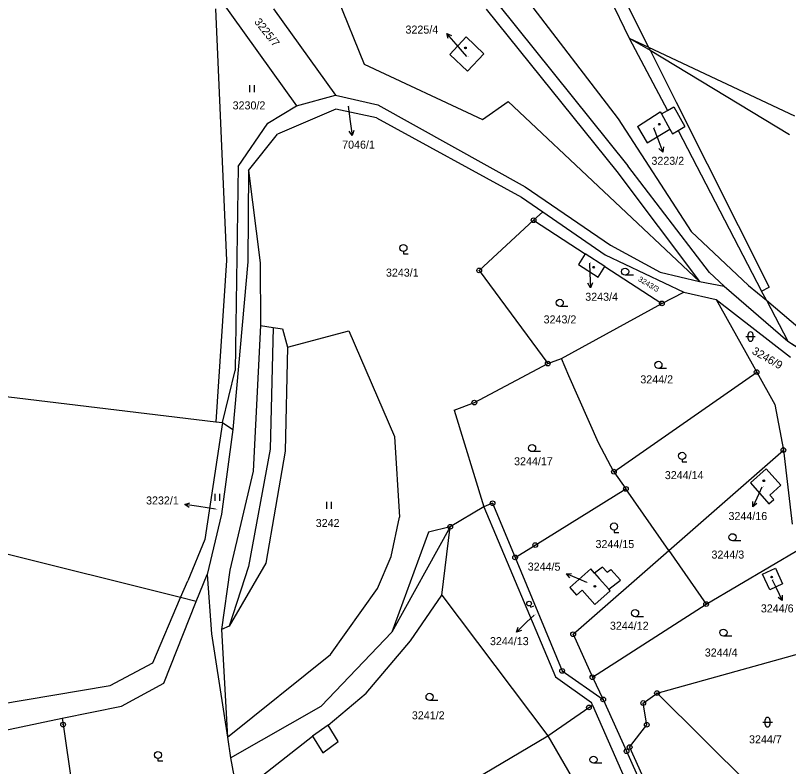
# Model space of a CAD drawing. Extents: x -593183 to -588034, y -1130415 to -1124994.
# Drawn here: x -592665.8 to -592501.6, y -1127991.1 to -1127831.6 of the extents above; entities that cross this region are included whole.
import ezdxf

# ---------------------------------------------------------------- set-up
doc = ezdxf.new("R2010")
doc.units = 0
for name, color, linetype in [('Vrstva 1', 7, 'Continuous'), ('Vrstva 16', 7, 'Continuous'), ('Vrstva 18', 7, 'Continuous'), ('Vrstva 19', 7, 'Continuous'), ('Vrstva 24', 7, 'Continuous'), ('Vrstva 25', 7, 'Continuous'), ('Vrstva 4', 7, 'Continuous')]:
    doc.layers.add(name, color=color, linetype=linetype)

msp = doc.modelspace()

# ---------------------------------------------------------------- linework, layer by layer
at = {"layer": 'Vrstva 1'}
for p, q in [((-592586.82, -1127789.77), (-592537.75, -1127853.56)), ((-592546.51, -1127808.32), (-592531.34, -1127838.36)), ((-592604.42, -1127810.45), (-592591.77, -1127841.97)), ((-592548.28, -1127810.16), (-592535.41, -1127836.44)), ((-592623.45, -1127826.59), (-592606.13, -1127850.85)), ((-592563.39, -1127829.08), (-592535.76, -1127863.57)), ((-592623.29, -1127830.23), (-592621.01, -1127883.66)), ((-592611, -1127830.22), (-592597.81, -1127848.59)), ((-592565.79, -1127830.28), (-592538.07, -1127864.74)), ((-592573.57, -1127839.96), (-592570.08, -1127836.18)), ((-592570.08, -1127836.18), (-592566.29, -1127839.82)), ((-592535.41, -1127836.44), (-592527.31, -1127851.81)), ((-592531.34, -1127838.36), (-592531.01, -1127839.01)), ((-592531.01, -1127839.01), (-592501.41, -1127856.93)), ((-592531.01, -1127839.01), (-592525.43, -1127850.05)), ((-592569.8, -1127843.47), (-592573.57, -1127839.96)), ((-592566.29, -1127839.82), (-592569.8, -1127843.47)), ((-592591.77, -1127841.97), (-592566.57, -1127853.74)), ((-592606.13, -1127850.85), (-592597.81, -1127848.59)), ((-592597.81, -1127848.59), (-592588.81, -1127850.6)), ((-592612.19, -1127854.48), (-592606.13, -1127850.85)), ((-592588.81, -1127850.6), (-592557.52, -1127868.04)), ((-592566.57, -1127853.74), (-592561.15, -1127849.89)), ((-592561.15, -1127849.89), (-592520.53, -1127888.15)), ((-592525.43, -1127850.05), (-592505.68, -1127889.36)), ((-592597.77, -1127851.54), (-592610.15, -1127856.84)), ((-592589.1, -1127853.39), (-592597.77, -1127851.54)), ((-592533.7, -1127855.19), (-592528.84, -1127852.1)), ((-592528.84, -1127852.1), (-592528.59, -1127852.54)), ((-592528.59, -1127852.54), (-592527.31, -1127851.81)), ((-592527.31, -1127851.81), (-592525.96, -1127851.05)), ((-592525.96, -1127851.05), (-592523.6, -1127855.21)), ((-592589.1, -1127853.39), (-592558.33, -1127870.19)), ((-592537.75, -1127853.56), (-592522.28, -1127877.52)), ((-592618.53, -1127863.68), (-592612.19, -1127854.48)), ((-592533.7, -1127855.19), (-592531.62, -1127858.66)), ((-592531.62, -1127858.66), (-592526.84, -1127855.8)), ((-592526.84, -1127855.8), (-592526.24, -1127856.8)), ((-592525.07, -1127856.1), (-592523.6, -1127855.21)), ((-592616.31, -1127864.53), (-592610.15, -1127856.84)), ((-592526.24, -1127856.8), (-592525.07, -1127856.1)), ((-592525.07, -1127856.1), (-592507.3, -1127890.18)), ((-592618.53, -1127863.68), (-592619.13, -1127907.06)), ((-592518.4, -1127886.2), (-592535.76, -1127863.57)), ((-592616.31, -1127864.53), (-592616.45, -1127883.98)), ((-592538.07, -1127864.74), (-592520.53, -1127888.15)), ((-592557.52, -1127868.04), (-592539.42, -1127880.42)), ((-592558.33, -1127870.19), (-592553.81, -1127873.31)), ((-592553.81, -1127873.31), (-592555.75, -1127875.11)), ((-592553.81, -1127873.31), (-592540.55, -1127882.46)), ((-592555.75, -1127875.11), (-592567.29, -1127885.78)), ((-592555.75, -1127875.11), (-592544.77, -1127882.24)), ((-592522.28, -1127877.52), (-592510.12, -1127889)), ((-592539.42, -1127880.42), (-592528.88, -1127886.14)), ((-592621.01, -1127883.66), (-592623.23, -1127917.93)), ((-592544.77, -1127882.24), (-592546.24, -1127884.5)), ((-592540.58, -1127884.96), (-592544.77, -1127882.24)), ((-592540.55, -1127882.46), (-592523.86, -1127890.37)), ((-592616.45, -1127883.98), (-592619.66, -1127919.53)), ((-592546.24, -1127884.5), (-592542.05, -1127887.22)), ((-592542.05, -1127887.22), (-592540.58, -1127884.96)), ((-592540.58, -1127884.96), (-592528.5, -1127892.8)), ((-592567.29, -1127885.78), (-592552.73, -1127905.56)), ((-592528.88, -1127886.14), (-592520.53, -1127888.15)), ((-592515.29, -1127889.1), (-592518.4, -1127886.2)), ((-592520.53, -1127888.15), (-592515.29, -1127889.1)), ((-592515.29, -1127889.1), (-592501.77, -1127900.77)), ((-592510.12, -1127889), (-592506.29, -1127892.12)), ((-592507.3, -1127890.18), (-592505.68, -1127889.36)), ((-592506.29, -1127892.12), (-592507.3, -1127890.18)), ((-592528.5, -1127892.8), (-592523.86, -1127890.37)), ((-592523.86, -1127890.37), (-592516.97, -1127891.93)), ((-592516.97, -1127891.93), (-592501.14, -1127904.21)), ((-592516.97, -1127891.93), (-592508.36, -1127907.36)), ((-592549.85, -1127904.45), (-592528.5, -1127892.8)), ((-592506.29, -1127892.12), (-592501.77, -1127900.77)), ((-592608.05, -1127902.07), (-592595, -1127898.63)), ((-592595, -1127898.63), (-592585.32, -1127921.02)), ((-592501.77, -1127900.77), (-592465.93, -1127923.67)), ((-592608.05, -1127902.07), (-592608.55, -1127924.16)), ((-592552.73, -1127905.56), (-592549.85, -1127904.45)), ((-592548.23, -1127908.14), (-592549.85, -1127904.45)), ((-592568.33, -1127913.85), (-592552.73, -1127905.56)), ((-592621.84, -1127918.1), (-592619.13, -1127907.06)), ((-592541.95, -1127922.42), (-592548.23, -1127908.14)), ((-592538.7, -1127928.51), (-592508.36, -1127907.36)), ((-592508.36, -1127907.36), (-592504.47, -1127914.27)), ((-592678.52, -1127911.3), (-592623.23, -1127917.93)), ((-592572.59, -1127915.48), (-592568.33, -1127913.85)), ((-592504.47, -1127914.27), (-592502.69, -1127923.91)), ((-592572.59, -1127915.48), (-592566.29, -1127935.99)), ((-592621.84, -1127918.1), (-592625.55, -1127942.92)), ((-592623.23, -1127917.93), (-592621.84, -1127918.1)), ((-592621.84, -1127918.1), (-592619.66, -1127919.53)), ((-592619.66, -1127919.53), (-592622.01, -1127937.52)), ((-592585.32, -1127921.02), (-592584.22, -1127938.14)), ((-592538.7, -1127928.51), (-592541.95, -1127922.42)), ((-592608.55, -1127924.16), (-592612.61, -1127947.94)), ((-592527.04, -1127945.25), (-592502.69, -1127923.91)), ((-592502.69, -1127923.91), (-592500.79, -1127939.63)), ((-592509.69, -1127930.86), (-592506.32, -1127927.88)), ((-592506.32, -1127927.88), (-592503.21, -1127931.4)), ((-592538.7, -1127928.51), (-592536.15, -1127932.18)), ((-592509.69, -1127930.86), (-592505.76, -1127935.32)), ((-592555.41, -1127944.09), (-592536.15, -1127932.18)), ((-592527.04, -1127945.25), (-592536.15, -1127932.18)), ((-592503.21, -1127931.4), (-592505.57, -1127933.49)), ((-592505.76, -1127935.32), (-592504.73, -1127934.41)), ((-592504.73, -1127934.41), (-592505.57, -1127933.49)), ((-592566.29, -1127935.99), (-592573.44, -1127940.22)), ((-592564.45, -1127935.22), (-592566.29, -1127935.99)), ((-592566.29, -1127935.99), (-592551.12, -1127972.04)), ((-592564.45, -1127935.22), (-592559.67, -1127946.73)), ((-592622.01, -1127937.52), (-592625.1, -1127950.32)), ((-592586.01, -1127946.54), (-592584.22, -1127938.14)), ((-592630.74, -1127955.24), (-592690.67, -1127940.34)), ((-592573.44, -1127940.22), (-592585.85, -1127962.59)), ((-592625.55, -1127942.92), (-592629.22, -1127951.69)), ((-592559.67, -1127946.73), (-592555.41, -1127944.09)), ((-592547.34, -1127963.04), (-592527.04, -1127945.25)), ((-592527.04, -1127945.25), (-592519.1, -1127956.63)), ((-592519.1, -1127956.63), (-592498.92, -1127944.73)), ((-592588.9, -1127953.28), (-592586.01, -1127946.54)), ((-592559.67, -1127946.73), (-592549.69, -1127970.8)), ((-592612.61, -1127947.94), (-592620.38, -1127961.3)), ((-592548.07, -1127953.1), (-592543.62, -1127949.14)), ((-592542.82, -1127950.04), (-592543.62, -1127949.14)), ((-592541.14, -1127948.79), (-592542.82, -1127950.04)), ((-592541.14, -1127948.79), (-592540.13, -1127949.88)), ((-592540.13, -1127949.88), (-592539.36, -1127949.26)), ((-592539.36, -1127949.26), (-592537.28, -1127951.53)), ((-592507.13, -1127950.28), (-592504.39, -1127949)), ((-592504.39, -1127949), (-592502.84, -1127952.31)), ((-592627.4, -1127956.08), (-592625.1, -1127950.32)), ((-592625.1, -1127950.32), (-592624.17, -1127962.93)), ((-592505.59, -1127953.58), (-592507.13, -1127950.28)), ((-592630.74, -1127955.24), (-592629.22, -1127951.69)), ((-592539.77, -1127953.49), (-592537.28, -1127951.53)), ((-592502.84, -1127952.31), (-592505.59, -1127953.58)), ((-592598.87, -1127967.31), (-592588.9, -1127953.28)), ((-592548.07, -1127953.1), (-592546.62, -1127954.73)), ((-592546.62, -1127954.73), (-592545.42, -1127953.66)), ((-592545.42, -1127953.66), (-592542.71, -1127956.7)), ((-592542.71, -1127956.7), (-592539.48, -1127953.82)), ((-592539.48, -1127953.82), (-592539.77, -1127953.49)), ((-592636.65, -1127969.08), (-592630.74, -1127955.24)), ((-592627.4, -1127956.08), (-592630.74, -1127955.24)), ((-592634.31, -1127973.38), (-592627.4, -1127956.08)), ((-592543.24, -1127972.16), (-592519.1, -1127956.63)), ((-592620.38, -1127961.3), (-592622.03, -1127962.01)), ((-592622.03, -1127962.01), (-592620.78, -1127984.86)), ((-592624.17, -1127962.93), (-592620.78, -1127984.86)), ((-592600.9, -1127978.32), (-592585.85, -1127962.59)), ((-592547.34, -1127963.04), (-592543.24, -1127972.16)), ((-592529.53, -1127975.52), (-592491.96, -1127965.07)), ((-592620.78, -1127984.86), (-592598.87, -1127967.31)), ((-592645.69, -1127973.89), (-592636.65, -1127969.08)), ((-592551.12, -1127972.04), (-592543.48, -1127977.55)), ((-592549.69, -1127970.8), (-592540.94, -1127976.88)), ((-592543.24, -1127972.16), (-592540.94, -1127976.88)), ((-592687.87, -1127981.06), (-592645.69, -1127973.89)), ((-592643.3, -1127978.28), (-592634.31, -1127973.38)), ((-592532.46, -1127977.63), (-592529.53, -1127975.52)), ((-592529.53, -1127975.52), (-592504.02, -1128000.74)), ((-592540.94, -1127976.88), (-592536.01, -1127987.86)), ((-592655.88, -1127980.87), (-592643.3, -1127978.28)), ((-592620.1, -1127989.27), (-592600.9, -1127978.32)), ((-592552.74, -1127984.59), (-592543.99, -1127978.58)), ((-592543.99, -1127978.58), (-592543.23, -1127978.11)), ((-592543.23, -1127978.11), (-592543.48, -1127977.55)), ((-592543.23, -1127978.11), (-592528.89, -1128010.56)), ((-592531.72, -1127982.26), (-592532.46, -1127977.63)), ((-592691.22, -1127988.24), (-592655.88, -1127980.87)), ((-592655.88, -1127980.87), (-592655.69, -1127982.21)), ((-592655.69, -1127982.21), (-592648.04, -1128035.39)), ((-592535.34, -1127986.99), (-592531.72, -1127982.26)), ((-592620.78, -1127984.86), (-592620.1, -1127989.27)), ((-592572.2, -1127996.11), (-592552.74, -1127984.59)), ((-592535.34, -1127986.99), (-592527.42, -1128004.73)), ((-592536.01, -1127987.86), (-592506.75, -1128053.34)), ((-592620.1, -1127989.27), (-592618.71, -1127997.15))]:
    msp.add_line(p, q, dxfattribs=at)
at = {"layer": 'Vrstva 16'}
for p, q in [((-592569.9, -1127840.37), (-592572.21, -1127837.74)), ((-592595.15, -1127850.92), (-592594.68, -1127854.17)), ((-592530.27, -1127855.51), (-592529.36, -1127857.86)), ((-592543.86, -1127884.22), (-592543.78, -1127886.44)), ((-592507.23, -1127931.77), (-592507.91, -1127933.24)), ((-592623.3, -1127936.47), (-592626.87, -1127935.92)), ((-592544.43, -1127952.04), (-592546.03, -1127951.36)), ((-592505.1, -1127951.48), (-592504.25, -1127953.19)), ((-592555.62, -1127958.96), (-592557.23, -1127960.49))]:
    msp.add_line(p, q, dxfattribs=at)
at = {"layer": 'Vrstva 24'}
for centre, radius in [((-592555.75, -1127875.11), 0.5), ((-592555.75, -1127875.11), 0.0327), ((-592567.29, -1127885.78), 0.5), ((-592567.29, -1127885.78), 0.0327), ((-592528.5, -1127892.8), 0.5), ((-592528.5, -1127892.8), 0.0327), ((-592552.73, -1127905.56), 0.5), ((-592552.73, -1127905.56), 0.0327), ((-592508.36, -1127907.36), 0.5), ((-592508.36, -1127907.36), 0.0327), ((-592568.33, -1127913.85), 0.5), ((-592568.33, -1127913.85), 0.0327), ((-592502.69, -1127923.91), 0.5), ((-592502.69, -1127923.91), 0.0327), ((-592538.7, -1127928.51), 0.5), ((-592538.7, -1127928.51), 0.0327), ((-592536.15, -1127932.18), 0.5), ((-592536.15, -1127932.18), 0.0327), ((-592564.45, -1127935.22), 0.5), ((-592564.45, -1127935.22), 0.0327), ((-592573.44, -1127940.22), 0.5), ((-592573.44, -1127940.22), 0.0327), ((-592555.41, -1127944.09), 0.5), ((-592555.41, -1127944.09), 0.0327), ((-592559.67, -1127946.73), 0.5), ((-592559.67, -1127946.73), 0.0327), ((-592519.1, -1127956.63), 0.5), ((-592519.1, -1127956.63), 0.0327), ((-592547.34, -1127963.04), 0.5), ((-592547.34, -1127963.04), 0.0327), ((-592549.69, -1127970.8), 0.5), ((-592549.69, -1127970.8), 0.0327), ((-592543.24, -1127972.16), 0.5), ((-592543.24, -1127972.16), 0.0327), ((-592529.53, -1127975.52), 0.5), ((-592529.53, -1127975.52), 0.0327), ((-592540.94, -1127976.88), 0.5), ((-592540.94, -1127976.88), 0.0327), ((-592532.46, -1127977.63), 0.5), ((-592543.99, -1127978.58), 0.5), ((-592543.99, -1127978.58), 0.0327), ((-592532.46, -1127977.63), 0.0327), ((-592655.69, -1127982.21), 0.5), ((-592655.69, -1127982.21), 0.0327), ((-592531.72, -1127982.26), 0.5), ((-592531.72, -1127982.26), 0.0327), ((-592535.34, -1127986.99), 0.5), ((-592535.34, -1127986.99), 0.0327), ((-592536.01, -1127987.86), 0.5), ((-592536.01, -1127987.86), 0.0327)]:
    msp.add_circle(centre, radius, dxfattribs=at)
at = {"layer": 'Vrstva 25'}
for p, q in [((-592572.21, -1127837.74), (-592574.19, -1127835.49)), ((-592616.06, -1127846.44), (-592616.06, -1127847.94)), ((-592615.04, -1127847.94), (-592615.04, -1127846.44)), ((-592594.68, -1127854.17), (-592594.25, -1127857.14)), ((-592529.36, -1127857.86), (-592528.28, -1127860.66)), ((-592583.39, -1127881.76), (-592583.39, -1127882.26)), ((-592583.39, -1127882.26), (-592582.37, -1127882.26)), ((-592543.78, -1127886.44), (-592543.68, -1127889.44)), ((-592534.55, -1127886.79), (-592536.3, -1127886.79)), ((-592548.44, -1127893.41), (-592550.19, -1127893.41)), ((-592510.66, -1127899.82), (-592508.66, -1127899.82)), ((-592510.16, -1127900.32), (-592510.16, -1127899.32)), ((-592509.16, -1127899.32), (-592509.16, -1127900.32)), ((-592527.48, -1127906.58), (-592529.23, -1127906.58)), ((-592554.31, -1127924.25), (-592556.06, -1127924.25)), ((-592524.19, -1127925.9), (-592524.19, -1127926.4)), ((-592524.19, -1127926.4), (-592523.17, -1127926.4)), ((-592623.45, -1127933.18), (-592623.45, -1127934.68)), ((-592622.43, -1127934.68), (-592622.43, -1127933.18)), ((-592507.91, -1127933.24), (-592509.17, -1127935.96)), ((-592626.87, -1127935.92), (-592629.84, -1127935.47)), ((-592599.72, -1127934.88), (-592599.72, -1127936.38)), ((-592598.7, -1127936.38), (-592598.7, -1127934.88)), ((-592538.66, -1127940.9), (-592538.66, -1127941.4)), ((-592538.66, -1127941.4), (-592537.64, -1127941.4)), ((-592511.74, -1127943.18), (-592513.49, -1127943.18)), ((-592546.03, -1127951.36), (-592548.79, -1127950.18)), ((-592504.25, -1127953.19), (-592502.91, -1127955.88)), ((-592556.49, -1127956.97), (-592556.35, -1127957.28)), ((-592556.35, -1127957.28), (-592555.72, -1127957)), ((-592557.23, -1127960.49), (-592559.4, -1127962.56)), ((-592532.43, -1127959.3), (-592534.18, -1127959.3)), ((-592513.66, -1127963.43), (-592515.41, -1127963.43)), ((-592576.1, -1127977.07), (-592577.85, -1127977.07)), ((-592507.03, -1127981.7), (-592505.03, -1127981.7)), ((-592506.53, -1127982.2), (-592506.53, -1127981.2)), ((-592505.53, -1127981.2), (-592505.53, -1127982.2)), ((-592635.54, -1127989.41), (-592635.54, -1127989.91)), ((-592635.54, -1127989.91), (-592634.52, -1127989.91)), ((-592541.27, -1127990.41), (-592543.02, -1127990.41))]:
    msp.add_line(p, q, dxfattribs=at)
for points in [[(-592573.91, -1127836.57), (-592574.19, -1127835.49), (-592573.15, -1127835.91)], [(-592593.9, -1127856.08), (-592594.25, -1127857.14), (-592594.89, -1127856.22)], [(-592528.17, -1127859.55), (-592528.28, -1127860.66), (-592529.11, -1127859.91)], [(-592543.21, -1127888.42), (-592543.68, -1127889.44), (-592544.21, -1127888.46)], [(-592628.92, -1127936.11), (-592629.84, -1127935.47), (-592628.77, -1127935.12)], [(-592508.3, -1127935.26), (-592509.17, -1127935.96), (-592509.2, -1127934.84)], [(-592548.07, -1127951.04), (-592548.79, -1127950.18), (-592547.67, -1127950.12)], [(-592502.91, -1127954.76), (-592502.91, -1127955.88), (-592503.81, -1127955.2)], [(-592558.33, -1127962.23), (-592559.4, -1127962.56), (-592559.02, -1127961.51)]]:
    msp.add_lwpolyline(points, dxfattribs=at)
for centre, radius in [((-592570.22, -1127838.53), 0.175), ((-592570.22, -1127838.53), 0.15), ((-592529.05, -1127854.74), 0.175), ((-592529.05, -1127854.74), 0.15), ((-592583.39, -1127881.01), 0.75), ((-592542.98, -1127885.1), 0.175), ((-592542.98, -1127885.1), 0.15), ((-592536.3, -1127886.04), 0.75), ((-592550.19, -1127892.66), 0.75), ((-592529.23, -1127905.83), 0.75), ((-592556.06, -1127923.5), 0.75), ((-592524.19, -1127925.15), 0.75), ((-592506.84, -1127930.44), 0.175), ((-592506.84, -1127930.44), 0.15), ((-592538.66, -1127940.15), 0.75), ((-592513.49, -1127942.43), 0.75), ((-592505.19, -1127950.88), 0.175), ((-592505.19, -1127950.88), 0.15), ((-592542.73, -1127952.86), 0.175), ((-592542.73, -1127952.86), 0.15), ((-592556.69, -1127956.52), 0.502), ((-592534.18, -1127958.55), 0.75), ((-592515.41, -1127962.68), 0.75), ((-592577.85, -1127976.32), 0.75), ((-592635.54, -1127988.66), 0.75), ((-592543.02, -1127989.66), 0.75)]:
    msp.add_circle(centre, radius, dxfattribs=at)
for centre, start, end in [((-592509.66, -1127899.32), 90, 180), ((-592509.66, -1127899.32), 0, 90), ((-592509.66, -1127900.32), 180, 270), ((-592509.66, -1127900.32), 270, 0), ((-592506.03, -1127981.2), 90, 180), ((-592506.03, -1127982.2), 180, 270), ((-592506.03, -1127981.2), 0, 90), ((-592506.03, -1127982.2), 270, 0)]:
    msp.add_arc(centre, 0.5, start, end, dxfattribs=at)
at = {"layer": 'Vrstva 4'}
for p, q in [((-592535.41, -1127836.44), (-592531.34, -1127838.36)), ((-592535.41, -1127836.44), (-592531.01, -1127839.01)), ((-592531.34, -1127838.36), (-592500.3, -1127852.98)), ((-592528.59, -1127852.54), (-592526.84, -1127855.8)), ((-592616.31, -1127864.53), (-592613.81, -1127884.17)), ((-592613.81, -1127884.17), (-592613.76, -1127897.49)), ((-592506.29, -1127892.12), (-592496.97, -1127900.04)), ((-592613.76, -1127897.49), (-592615.33, -1127928.42)), ((-592613.76, -1127897.49), (-592611.08, -1127897.88)), ((-592611.08, -1127897.88), (-592611.68, -1127923.72)), ((-592611.08, -1127897.88), (-592609.06, -1127898.17)), ((-592609.06, -1127898.17), (-592608.05, -1127902.07)), ((-592501.77, -1127900.77), (-592466.14, -1127924.13)), ((-592611.68, -1127923.72), (-592616.34, -1127948.62)), ((-592615.33, -1127928.42), (-592620.27, -1127949.39)), ((-592573.44, -1127940.22), (-592578.08, -1127941.35)), ((-592575.22, -1127954.76), (-592573.44, -1127940.22)), ((-592578.08, -1127941.35), (-592585.85, -1127962.59)), ((-592620.27, -1127949.39), (-592622.03, -1127962.01)), ((-592616.34, -1127948.62), (-592620.38, -1127961.3)), ((-592542.82, -1127950.04), (-592541.82, -1127951.18)), ((-592541.82, -1127951.18), (-592539.77, -1127953.49)), ((-592581.91, -1127964.43), (-592575.22, -1127954.76)), ((-592575.22, -1127954.76), (-592552.74, -1127984.59)), ((-592591.28, -1127975.52), (-592581.91, -1127964.43)), ((-592599.4, -1127982.34), (-592591.28, -1127975.52)), ((-592599.4, -1127982.34), (-592602.73, -1127984.7)), ((-592597.27, -1127985.81), (-592599.4, -1127982.34)), ((-592618.71, -1127997.15), (-592602.73, -1127984.7)), ((-592602.73, -1127984.7), (-592600.55, -1127988.18)), ((-592552.74, -1127984.59), (-592541.87, -1128003.22)), ((-592600.55, -1127988.18), (-592597.27, -1127985.81))]:
    msp.add_line(p, q, dxfattribs=at)

# ---------------------------------------------------------------- texts
at = {"layer": 'Vrstva 16'}
for s, p in [('3225/4', (-592582.96, -1127835.49)), ('7046/1', (-592596.41, -1127859.92)), ('3223/2', (-592530.72, -1127863.35)), ('3243/4', (-592544.77, -1127892.22)), ('3232/1', (-592638.07, -1127935.47)), ('3244/16', (-592514.34, -1127938.78)), ('3244/6', (-592507.47, -1127958.39)), ('3244/13', (-592565.01, -1127965.34))]:
    msp.add_text(s, height=1.7, dxfattribs=at).set_placement(p)
msp.add_text('3244/5', height=1.7, rotation=359.7598, dxfattribs=at).set_placement((-592557, -1127949.51))
at = {"layer": 'Vrstva 18'}
for s, height, rotation, p in [('3225/7', 1.7, 308.3764, (-592615.19, -1127833.03)), ('3243/3', 1.14, 328.8932, (-592533.65, -1127887.93)), ('3246/9', 1.7, 330.1672, (-592509.51, -1127903.37))]:
    msp.add_text(s, height=height, rotation=rotation, dxfattribs=at).set_placement(p)
for s, height, p in [('3230/2', 1.7, (-592619.68, -1127851.59)), ('7046/1', 0.1, (-592595.15, -1127850.92)), ('3243/1', 1.7, (-592587.11, -1127887.09)), ('3243/2', 1.7, (-592553.62, -1127897.03)), ('3244/2', 1.7, (-592533.07, -1127909.76)), ('3244/17', 1.7, (-592559.89, -1127927.15)), ('3244/14', 1.7, (-592527.87, -1127930.09)), ('3232/1', 0.1, (-592623.3, -1127936.47)), ('3242', 1.7, (-592602.03, -1127940.26)), ('3244/15', 1.7, (-592542.59, -1127944.73)), ('3244/3', 1.7, (-592517.96, -1127946.96)), ('3244/13', 0.1, (-592555.62, -1127958.96)), ('3244/12', 1.7, (-592539.53, -1127962.07)), ('3244/4', 1.7, (-592519.38, -1127967.76)), ('3241/2', 1.7, (-592581.6, -1127981.09)), ('3244/7', 1.7, (-592509.98, -1127986.19))]:
    msp.add_text(s, height=height, dxfattribs=at).set_placement(p)
at = {"layer": 'Vrstva 19'}
for s, p in [('3225/4', (-592569.9, -1127840.37)), ('3223/2', (-592530.27, -1127855.51)), ('3243/4', (-592543.86, -1127884.22)), ('3244/16', (-592507.23, -1127931.77)), ('3244/5', (-592544.43, -1127952.04)), ('3244/6', (-592505.1, -1127951.48))]:
    msp.add_text(s, height=0.1, dxfattribs=at).set_placement(p)

doc.saveas('drawing.dxf')
